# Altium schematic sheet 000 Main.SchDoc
size A3; Organization: Linear Computing Inc.; Address1: 6415 Northwest Drive; Address2: Mississauga, ON, L4V1X1; Address3: Canada; SheetNumber: 1; SheetTotal: 20
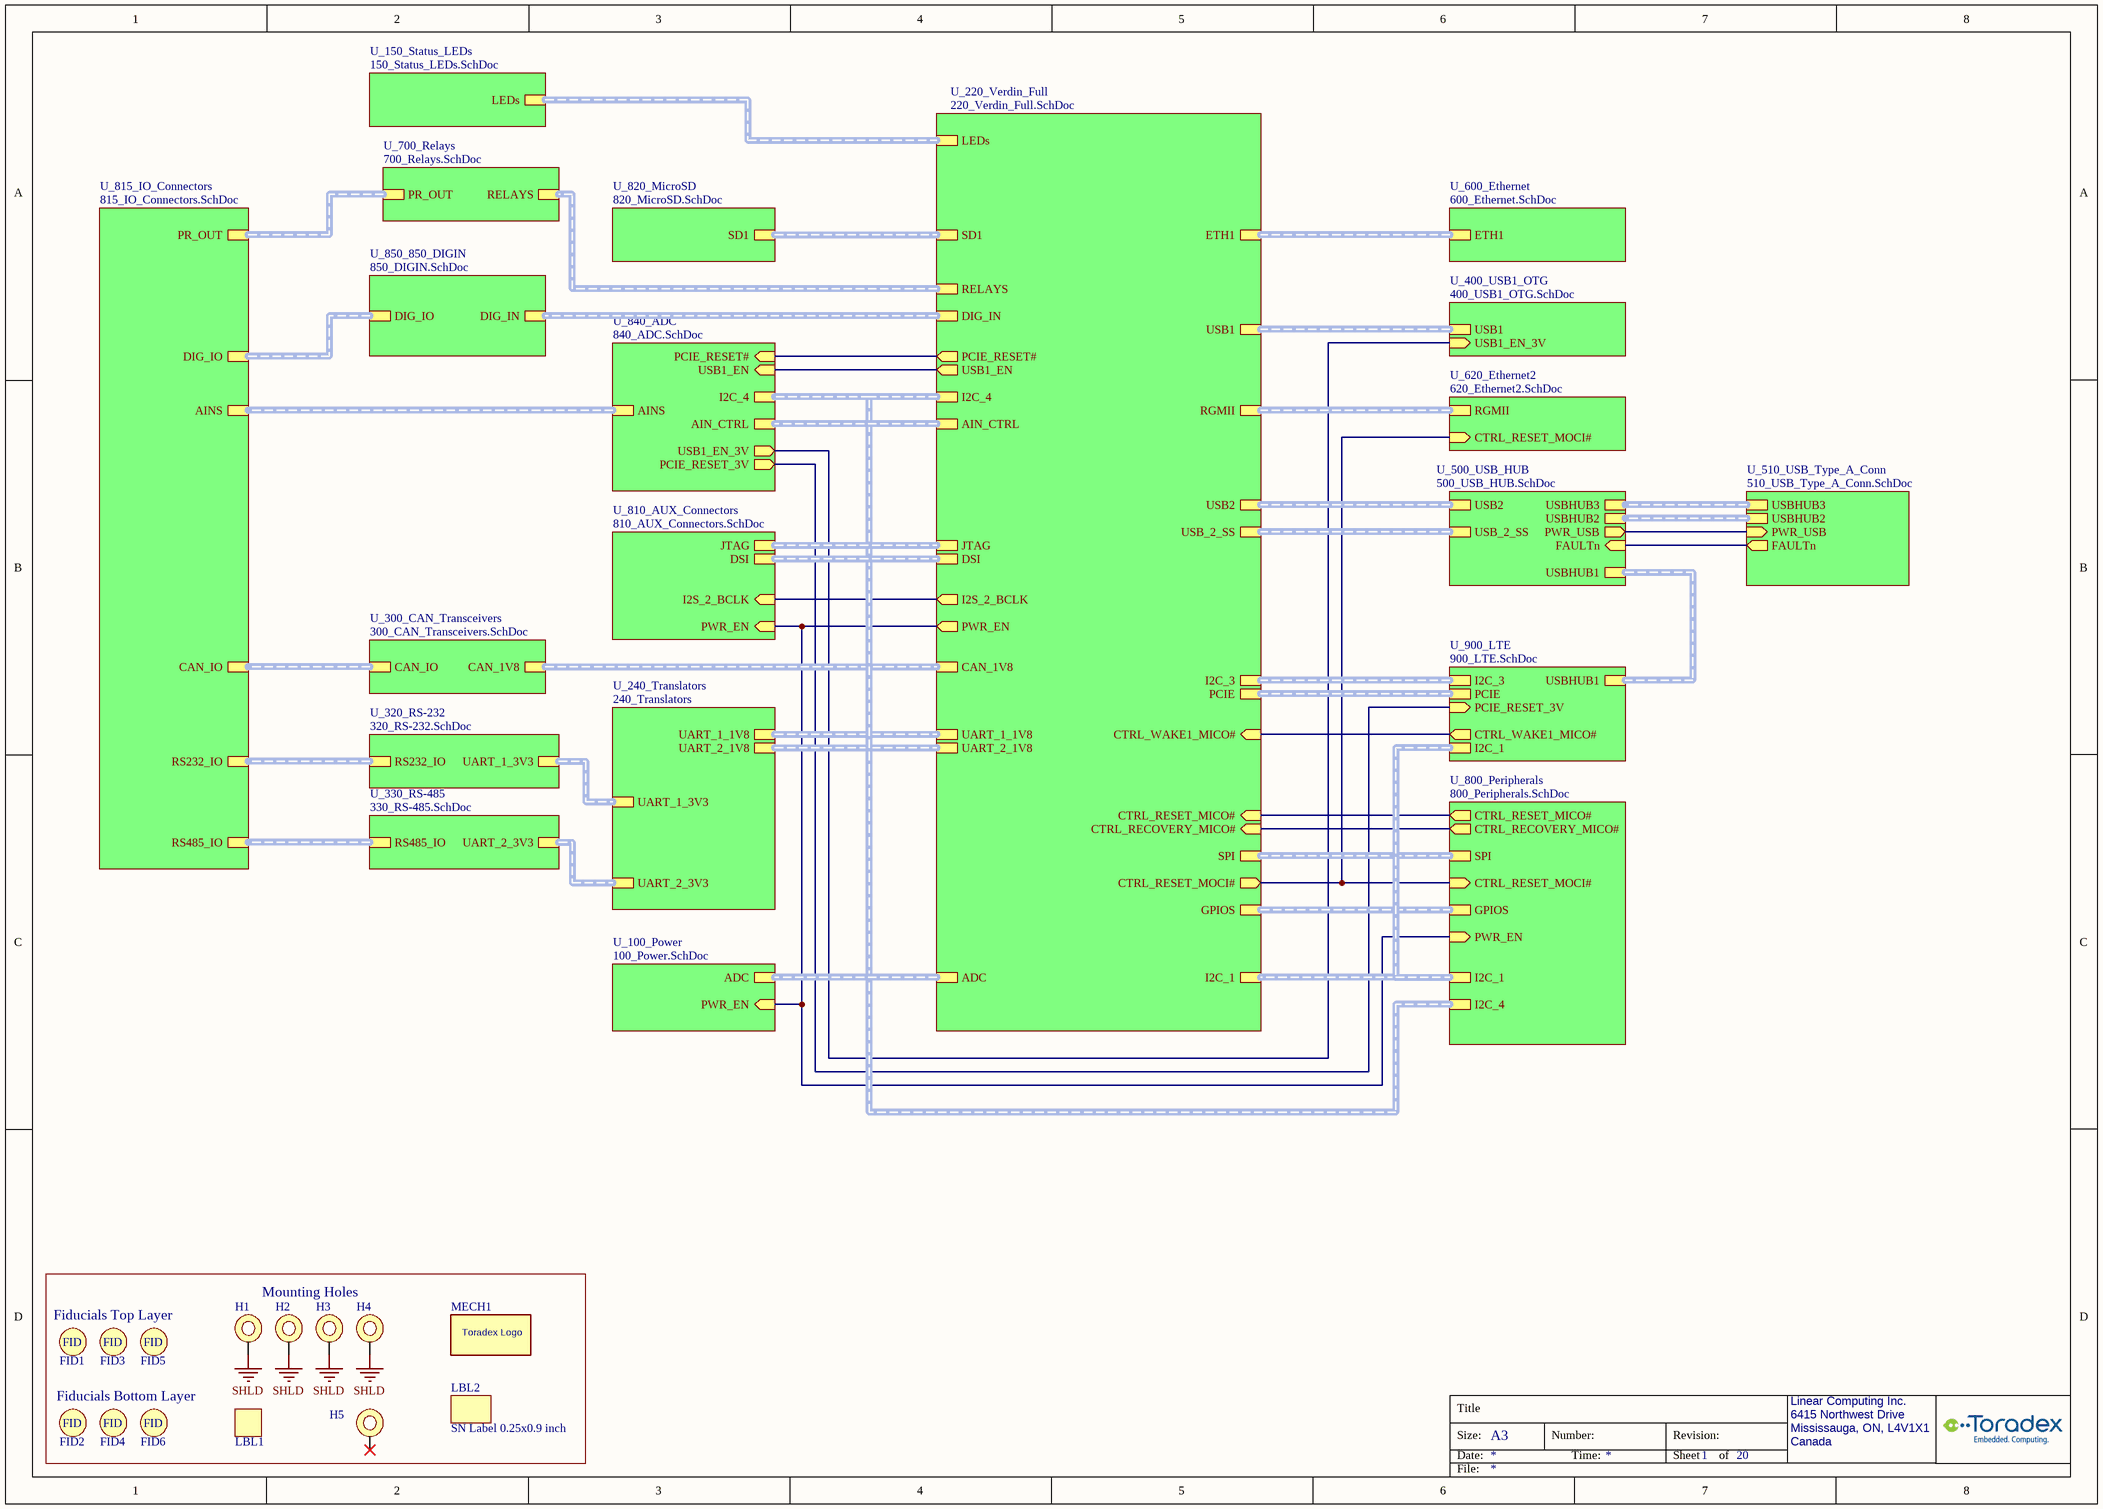
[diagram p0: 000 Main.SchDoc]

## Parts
FID1  Fiducial round  [FID_40X120_RND]  (value not drawn)  (no BOM)
FID2  Fiducial round  [FID_40X120_RND]  (value not drawn)  (no BOM)
FID3  Fiducial round  [FID_40X120_RND]  (value not drawn)  (no BOM)
FID4  Fiducial round  [FID_40X120_RND]  (value not drawn)  (no BOM)
FID5  Fiducial round  [FID_40X120_RND]  (value not drawn)  (no BOM)
FID6  Fiducial round  [FID_40X120_RND]  (value not drawn)  (no BOM)
H1  Hole  [MTG_HOLE_0.125]  (value not drawn)  (no BOM)
H2  Hole  [MTG_HOLE_0.125]  (value not drawn)  (no BOM)
H3  Hole  [MTG_HOLE_0.125]  (value not drawn)  (no BOM)
H4  Hole  [MTG_HOLE_0.125]  (value not drawn)  (no BOM)
H5  Hole  [MTG_HOLE_0.125]  (value not drawn)  (no BOM)
LBL1  SN Label 10x10mm  [LABEL_10x10mm_ALT]  (value not drawn)  (no BOM)
LBL2  SN Label 0.25x0.9 inch  [LABEL_0.25x0.9IN]  (no BOM)
MECH1  MECH-Toradex_Logo  [T_TORADEX_LOGO]  (value not drawn)  (no BOM)

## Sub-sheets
U_100_Power = 100_Power.SchDoc: PWR_EN (in), ADC (harness ADC)
U_150_Status_LEDs = 150_Status_LEDs.SchDoc: LEDs (harness LEDs)
U_220_Verdin_Full = 220_Verdin_Full.SchDoc: CTRL_RECOVERY_MICO# (in), CTRL_RESET_MICO# (in), CTRL_WAKE1_MICO# (in), ETH1 (harness ETH1), USB2 (harness USB2), USB1 (harness USB1), PCIE (harness PCIe), SPI (harness SPI), PWR_EN (out), AIN_CTRL (harness AIN_CTRL), CTRL_RESET_MOCI# (out), GPIOS (harness GPIOs), RGMII (harness RGMII), SD1 (harness SD1), CAN_1V8 (harness 2xCAN_1V8), UART_1_1V8 (harness UART_1_1V8), UART_2_1V8 (harness UART_2_1V8), RELAYS (harness RELAYS), I2C_1 (harness I2C_1), DIG_IN (harness DIG_IN), JTAG (harness JTAG), LEDs (harness LEDs), I2C_4 (harness I2C_4), DSI (harness DSI), I2S_2_BCLK (out), ADC (harness ADC), I2C_3 (harness I2C_3), USB1_EN (out), PCIE_RESET# (out), USB_2_SS (harness USB_2_SS)
U_240_Translators = 240_Translators: UART_1_1V8 (harness UART_1_1V8), UART_2_1V8 (harness UART_2_1V8), UART_2_3V3 (harness UART_2_3V3), UART_1_3V3 (harness UART_1_3V3)
U_300_CAN_Transceivers = 300_CAN_Transceivers.SchDoc: CAN_1V8 (harness 2xCAN_1V8), CAN_IO (harness CAN_IO)
U_320_RS-232 = 320_RS-232.SchDoc: UART_1_3V3 (harness UART_1_3V3), RS232_IO (harness RS232_IO)
U_330_RS-485 = 330_RS-485.SchDoc: UART_2_3V3 (harness UART_2_3V3), RS485_IO (harness RS485_IO)
U_400_USB1_OTG = 400_USB1_OTG.SchDoc: USB1_EN_3V (in), USB1 (harness USB1)
U_500_USB_HUB = 500_USB_HUB.SchDoc: USB2 (harness USB2), USBHUB1 (harness USBHUB1), USBHUB2 (harness USBHUB2), USBHUB3 (harness USBHUB3), PWR_USB (out), FAULTn (in), USB_2_SS (harness USB_2_SS)
U_510_USB_Type_A_Conn = 510_USB_Type_A_Conn.SchDoc: USBHUB2 (harness USBHUB2), USBHUB3 (harness USBHUB3), PWR_USB (in), FAULTn (out)
U_600_Ethernet = 600_Ethernet.SchDoc: ETH1 (harness ETH1)
U_620_Ethernet2 = 620_Ethernet2.SchDoc: RGMII (harness RGMII), CTRL_RESET_MOCI# (in)
U_700_Relays = 700_Relays.SchDoc: RELAYS (harness RELAYS), PR_OUT (harness PR_OUT)
U_800_Peripherals = 800_Peripherals.SchDoc: CTRL_RECOVERY_MICO# (out), CTRL_RESET_MICO# (out), I2C_1 (harness I2C_1), SPI (harness SPI), I2C_4 (harness I2C_4), PWR_EN (in), CTRL_RESET_MOCI# (in), GPIOS (harness GPIOs)
U_810_AUX_Connectors = 810_AUX_Connectors.SchDoc: JTAG (harness JTAG), DSI (harness DSI), I2S_2_BCLK (in), PWR_EN (in)
U_815_IO_Connectors = 815_IO_Connectors.SchDoc: PR_OUT (harness PR_OUT), DIG_IO (harness DIG_IO), AINS (harness AINS), CAN_IO (harness CAN_IO), RS232_IO (harness RS232_IO), RS485_IO (harness RS485_IO)
U_820_MicroSD = 820_MicroSD.SchDoc: SD1 (harness SD1)
U_840_ADC = 840_ADC.SchDoc: I2C_4 (harness I2C_4), AIN_CTRL (harness AIN_CTRL), AINS (harness AINS), USB1_EN (in), PCIE_RESET# (in), USB1_EN_3V (out), PCIE_RESET_3V (out)
U_850_850_DIGIN = 850_DIGIN.SchDoc: DIG_IN (harness DIG_IN), DIG_IO (harness DIG_IO)
U_900_LTE = 900_LTE.SchDoc: PCIE (harness PCIe), CTRL_WAKE1_MICO# (out), PCIE_RESET_3V (in), USBHUB1 (harness USBHUB1), I2C_1 (harness I2C_1), I2C_3 (harness I2C_3)

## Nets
SHLD: H1.0(MTG_HOLE) H2.0(MTG_HOLE) H3.0(MTG_HOLE) H4.0(MTG_HOLE)
(unnamed): sheet U_100_Power/PWR_EN, sheet U_220_Verdin_Full/PWR_EN, sheet U_800_Peripherals/PWR_EN, sheet U_810_AUX_Connectors/PWR_EN
(unnamed): sheet U_400_USB1_OTG/USB1_EN_3V, sheet U_840_ADC/USB1_EN_3V  [a separate net that carries the same name]
(unnamed): sheet U_220_Verdin_Full/CTRL_RECOVERY_MICO#, sheet U_800_Peripherals/CTRL_RECOVERY_MICO#  [a separate net that carries the same name]
(unnamed): sheet U_220_Verdin_Full/CTRL_RESET_MICO#, sheet U_800_Peripherals/CTRL_RESET_MICO#  [a separate net that carries the same name]
(unnamed): sheet U_220_Verdin_Full/CTRL_WAKE1_MICO#, sheet U_900_LTE/CTRL_WAKE1_MICO#  [a separate net that carries the same name]
(unnamed): sheet U_220_Verdin_Full/CTRL_RESET_MOCI#, sheet U_800_Peripherals/CTRL_RESET_MOCI#, sheet U_620_Ethernet2/CTRL_RESET_MOCI#  [a separate net that carries the same name]
(unnamed): sheet U_220_Verdin_Full/I2S_2_BCLK, sheet U_810_AUX_Connectors/I2S_2_BCLK  [a separate net that carries the same name]
(unnamed): sheet U_220_Verdin_Full/USB1_EN, sheet U_840_ADC/USB1_EN  [a separate net that carries the same name]
(unnamed): sheet U_220_Verdin_Full/PCIE_RESET#, sheet U_840_ADC/PCIE_RESET#  [a separate net that carries the same name]
(unnamed): sheet U_900_LTE/PCIE_RESET_3V, sheet U_840_ADC/PCIE_RESET_3V  [a separate net that carries the same name]
(unnamed): sheet U_500_USB_HUB/PWR_USB, sheet U_510_USB_Type_A_Conn/PWR_USB  [a separate net that carries the same name]
(unnamed): sheet U_500_USB_HUB/FAULTn, sheet U_510_USB_Type_A_Conn/FAULTn  [a separate net that carries the same name]

Not connected (* = marked no-connect by the designer): H5 0(MTG_HOLE)*

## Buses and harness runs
harness sheet U_100_Power/ADC = sheet U_220_Verdin_Full/ADC
harness sheet U_150_Status_LEDs/LEDs = sheet U_220_Verdin_Full/LEDs
harness sheet U_220_Verdin_Full/AIN_CTRL = sheet U_840_ADC/AIN_CTRL
harness sheet U_220_Verdin_Full/CAN_1V8 = sheet U_300_CAN_Transceivers/CAN_1V8
harness sheet U_220_Verdin_Full/DIG_IN = sheet U_850_850_DIGIN/DIG_IN
harness sheet U_220_Verdin_Full/DSI = sheet U_810_AUX_Connectors/DSI
harness sheet U_220_Verdin_Full/ETH1 = sheet U_600_Ethernet/ETH1
harness sheet U_220_Verdin_Full/GPIOS = sheet U_800_Peripherals/GPIOS
harness sheet U_220_Verdin_Full/I2C_1 = sheet U_800_Peripherals/I2C_1 = sheet U_900_LTE/I2C_1
harness sheet U_220_Verdin_Full/I2C_3 = sheet U_900_LTE/I2C_3
harness sheet U_220_Verdin_Full/I2C_4 = sheet U_800_Peripherals/I2C_4 = sheet U_840_ADC/I2C_4
harness sheet U_220_Verdin_Full/JTAG = sheet U_810_AUX_Connectors/JTAG
harness sheet U_220_Verdin_Full/PCIE = sheet U_900_LTE/PCIE
harness sheet U_220_Verdin_Full/RELAYS = sheet U_700_Relays/RELAYS
harness sheet U_220_Verdin_Full/RGMII = sheet U_620_Ethernet2/RGMII
harness sheet U_220_Verdin_Full/SD1 = sheet U_820_MicroSD/SD1
harness sheet U_220_Verdin_Full/SPI = sheet U_800_Peripherals/SPI
harness sheet U_220_Verdin_Full/UART_1_1V8 = sheet U_240_Translators/UART_1_1V8
harness sheet U_220_Verdin_Full/UART_2_1V8 = sheet U_240_Translators/UART_2_1V8
harness sheet U_220_Verdin_Full/USB1 = sheet U_400_USB1_OTG/USB1
harness sheet U_220_Verdin_Full/USB2 = sheet U_500_USB_HUB/USB2
harness sheet U_220_Verdin_Full/USB_2_SS = sheet U_500_USB_HUB/USB_2_SS
harness sheet U_240_Translators/UART_1_3V3 = sheet U_320_RS-232/UART_1_3V3
harness sheet U_240_Translators/UART_2_3V3 = sheet U_330_RS-485/UART_2_3V3
harness sheet U_300_CAN_Transceivers/CAN_IO = sheet U_815_IO_Connectors/CAN_IO
harness sheet U_320_RS-232/RS232_IO = sheet U_815_IO_Connectors/RS232_IO
harness sheet U_330_RS-485/RS485_IO = sheet U_815_IO_Connectors/RS485_IO
harness sheet U_500_USB_HUB/USBHUB1 = sheet U_900_LTE/USBHUB1
harness sheet U_500_USB_HUB/USBHUB2 = sheet U_510_USB_Type_A_Conn/USBHUB2
harness sheet U_500_USB_HUB/USBHUB3 = sheet U_510_USB_Type_A_Conn/USBHUB3
harness sheet U_700_Relays/PR_OUT = sheet U_815_IO_Connectors/PR_OUT
harness sheet U_815_IO_Connectors/AINS = sheet U_840_ADC/AINS
harness sheet U_815_IO_Connectors/DIG_IO = sheet U_850_850_DIGIN/DIG_IO

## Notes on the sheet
- Fiducials Top Layer
- Mounting Holes
- Fiducials Bottom Layer

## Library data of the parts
FID1-FID6 = 0000-Fiducial-round
H1-H5 = 000-Hole-125mil
LBL1 = 000-Label-10x10mm: Label for serial number 10x10mm
LBL2 = 000-Label-0.25x0.9IN: Label for Toradex serial number label 0.25x0.9 inch
MECH1 = MECH-Toradex_Logo: Toradex_Logo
